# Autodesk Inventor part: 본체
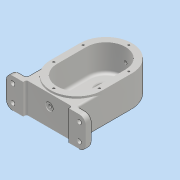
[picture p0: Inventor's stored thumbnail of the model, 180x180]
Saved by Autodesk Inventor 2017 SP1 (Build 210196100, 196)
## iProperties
Part Number: 본체
Material: 알루미늄 6061
Document SubType Name: Modeling
Designer: MRC
Density: 2.7 g/cm^3
Appearance: 알루미늄 - 평지
Mass: 756.449 g
Surface Area: 582.679 cm^2
Volume: 280.166 cm^3
Author: MRC
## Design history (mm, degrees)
sketch "스케치4"
  geometry: L1 (0, 0)-(0, -87); L2 (-40, 0)-(-40, -82); L3 (40, -82)-(40, 0); L4 (-40, -82)-(-61, -82); L5 (-61, -82)-(-61, -92); L6 (-61, -92)-(-35, -92); L7 (-35, -92)-(-35, -87); L8 (-35, -87)-(35, -87); L9 (35, -87)-(35, -92); L10 (35, -92)-(61, -92); L11 (61, -92)-(61, -82); L12 (61, -82)-(40, -82); A1 r 40 centre (0, 0) between (40, 0) and (-40, 0); 1 further point
  constraints: 26 end point, 7 perpendicular, 3 point on line, 2 midpoint, 2 point on circle, 2 tangent, 2 vertical, 1 centre point, 1 horizontal, 1 parallel
  dimensions: "d17" = 40 radius of A1; "d18" = 10 distance of L10.end L11.end; "d19" = 70 distance of L7.end L8.end; "d20" = 122 distance between parallel lines of L5 L11; "d21" = 61 distance from line of point (0, -43.5) L5; "d22" = 92 distance from line of L10 L1.start; "d23" = 5 distance of L8.end L9.end
extrude "돌출4" new body sketch "스케치4" distance "d24" = 46; taper "d25" = 0 deg
sketch "스케치5"
  geometry: L1 (0, 0)-(0, -45); L2 (-40, 0)-(-40, -45); L3 (40, -45)-(40, 0); A1 r 40 centre (0, 0) between (40, 0) and (-40, 0) reference; A2 r 40 centre (0, 0) between (40, 0) and (-40, 0); A3 r 40 centre (0, -45) between (-40, -45) and (40, -45); 1 further point
  constraints: 8 end point, 4 point on circle, 4 tangent, 2 centre point, 1 concentric, 1 midpoint, 1 parallel, 1 vertical
  dimensions: "d26" = 45 distance of L1.start L1.end
extrude "돌출5" join sketch "스케치5" distance "d27" = 3; taper "d28" = 0 deg
sketch "스케치6"
  geometry: L1 (0, 0)-(0, -45); L2 (-26, 0)-(-26, -45); L3 (26, -45)-(26, 0); A1 r 40 centre (0, 0) between (40, 0) and (-40, 0) reference; A2 r 26 centre (0, 0) between (26, 0) and (-26, 0); A3 r 26 centre (0, -45) between (-26, -45) and (26, -45); 1 further point
  constraints: 8 end point, 4 point on circle, 4 tangent, 2 centre point, 1 midpoint, 1 parallel, 1 vertical
  dimensions: "d29" = 26 radius of A2; "d30" = 45 distance of L1.start L1.end
extrude "돌출6" join sketch "스케치6" distance "d31" = 11; taper "d32" = 0 deg
sketch "스케치7"
  geometry: L1 (26, -45)-(26, 0) reference; L2 (-26, -45)-(-26, 0) reference; L3 (-26, -30)-(26, -30); A1 r 26 centre (0, 0) between (26, 0) and (-26, 0) reference
  constraints: 2 end point, 2 point on line, 1 perpendicular
  dimensions: "d33" = 30 distance from line of L3 A1.centre
extrude "돌출7" cut sketch "스케치7" distance "d34" = 3; taper "d35" = 0 deg
sketch "스케치8"
  geometry: L1 (0, 0)-(0, -45); L2 (-30, 0)-(-30, -45); L3 (30, -45)-(30, 0); A1 r 40 centre (0, -45) between (-40, -45) and (40, -45) reference; A2 r 40 centre (0, 0) between (40, 0) and (-40, 0) reference; A3 r 30 centre (0, 0) between (30, 0) and (-30, 0); A4 r 30 centre (0, -45) between (-30, -45) and (30, -45); 1 further point
  constraints: 8 end point, 4 point on circle, 4 tangent, 2 centre point, 1 midpoint, 1 parallel, 1 vertical
  dimensions: "d36" = 30 radius of A3
extrude "돌출8" cut sketch "스케치8" distance "d37" = 41; taper "d38" = 0 deg
hole "구멍1" diameter "d41" = 20; stored, may be unused: countersink angle "d45" = 90 deg, drill point angle "d47" = 0 deg; dims "d39" = 10, "d40" = 10, "d42" = 6, "d43" = 28, "d44" = 8, "d46" = 12
hole "구멍2" diameter "d50" = 22; stored, may be unused: countersink angle "d54" = 90 deg, drill point angle "d56" = 0 deg; dims "d48" = 10, "d49" = 10, "d51" = 6, "d52" = 28, "d53" = 8, "d55" = 100
sketch "스케치9"
  geometry: C1 r 11 at (0, 0) reference; C2 r 14 at (0, 0); A1 r 26 centre (0, 0) between (26, 0) and (-26, 0) reference
  constraints: 1 centre point, 1 coincident
  dimensions: "d57" = 28 diameter of C2
extrude "돌출9" cut sketch "스케치9" distance "d58" = 4; taper "d59" = 0 deg
fillet "모깎기4" dims "d60" = 10, "d61" = 5
sketch "스케치10"
  geometry: L1 (-101, 36)-(-101, 10) reference; L2 (-80, 0)-(-91, 0) reference; L3 (-80, 46)-(-80, 0) reference; L4 (-80, 46)-(-91, 46) reference; A1 r 10 centre (11, 36) between (21, 36) and (11, 46) reference; A2 r 10 centre (11, 10) between (11, 0) and (21, 10) reference; A3 r 10 centre (-91, 36) between (-91, 46) and (-101, 36) reference; A4 r 10 centre (-91, 10) between (-101, 10) and (-91, 0) reference; 1 further point
hole "구멍3" sketch "스케치10" at (-91, 10), (11, 36), (11, 10), (-91, 36) diameter "d62" = 6.6; stored, may be unused: countersink angle "d66" = 90 deg, drill point angle "d68" = 0 deg; dims "d63" = 6, "d64" = 11, "d65" = 2, "d67" = 10
node "작업 평면1"
sketch "스케치11"
  geometry: L1 (75, 49)-(-5, 49) reference; C1 r 6 at (35, 28); 1 further point
  constraints: 1 centre point, 1 vertical alignment
  dimensions: "d70" = 12 diameter of C1; "d71" = 21 distance from line of L1 C1.centre
extrude "돌출10" join sketch "스케치11" stored distance "d72" = 4; taper "d73" = 0 deg
hole "구멍4" diameter "d76" = 4.917; stored, may be unused: countersink angle "d80" = 90 deg, drill point angle "d82" = 0 deg; dims "d74" = 10, "d75" = 10, "d77" = 12, "d78" = 11, "d79" = 2, "d81" = 17.1
sketch "스케치12"
  geometry: L1 (0, 0)-(70, 0) reference; L2 (75, 49)-(-5, 49) reference; 3 further points
  constraints: 1 midpoint, 1 vertical alignment
  dimensions: "d83" = 21 distance from line of point (35, 28) L2
hole "구멍5" sketch "스케치12" at (35, 28) diameter "d84" = 4.917; stored, may be unused: countersink angle "d88" = 90 deg, drill point angle "d90" = 0 deg; dims "d85" = 12, "d86" = 12, "d87" = 1, "d89" = 17.1
sketch "스케치13"
  geometry: C1 r 14 at (0, 0) reference; 1 further point
  constraints: 1 vertical alignment
  dimensions: "d91" = 20 distance of C1.centre point (0, 20)
hole "구멍6" sketch "스케치13" at (0, 20) diameter "d92" = 3.242; stored, may be unused: countersink angle "d96" = 90 deg, drill point angle "d98" = 118 deg; dims "d93" = 8, "d94" = 12, "d95" = 1, "d97" = 10
sketch "스케치14"
  geometry: A1 r 30 centre (0, 0) between (30, 0) and (-30, 0) reference; 1 further point
  constraints: 1 vertical alignment
  dimensions: "d102" = 35 distance of A1.centre point (0, 35)
hole "구멍7" sketch "스케치14" at (0, 35) diameter "d103" = 3.242; stored, may be unused: countersink angle "d107" = 90 deg, drill point angle "d109" = 118 deg; dims "d104" = 8, "d105" = 12, "d106" = 1, "d108" = 10
sketch "스케치15"
  geometry: L1 (0, 0)-(0, -45); L2 (-35, 0)-(-35, -45); L3 (35, -45)-(35, 0); A1 r 40 centre (0, -45) between (-40, -45) and (40, -45) reference; A2 r 40 centre (0, 0) between (40, 0) and (-40, 0) reference; A3 r 35 centre (0, 0) between (35, 0) and (-35, 0); A4 r 35 centre (0, -45) between (-35, -45) and (35, -45); 6 further points
  constraints: 8 end point, 5 point on circle, 4 coincident, 4 tangent, 2 centre point, 1 midpoint, 1 parallel, 1 vertical
  dimensions: "d110" = 70 diameter of A4
hole "구멍8" sketch "스케치15" at (-35, 0), (35, 0), (35, -45), (-35, -45), (0, -80) diameter "d111" = 3.242; stored, may be unused: countersink angle "d115" = 90 deg, drill point angle "d117" = 118 deg; dims "d112" = 8, "d113" = 12, "d114" = 1, "d116" = 10
fillet "모깎기5" dims "d118" = 0.3
chamfer "모따기1" distance "d119" = 1; stored, may be unused: second distance "d120" = 2, angle "d121" = 45 deg
fillet "모깎기6" dims "d122" = 3
sketch "스케치16"
  geometry: L1 (32, -87)-(-32, -87) reference; L2 (-51, -92)-(-61, -92) reference; 2 further points
  constraints: 1 midpoint, 1 vertical alignment, 1 other
  dimensions: "d123" = 12 distance from line of point (0, -80) L2
feature "엠보싱1" sketch "스케치16" dims "d124" = 0.5, "d125" = 0
node "솔리드2"
pattern_circular "원형 패턴1" dims angle "d100" = 360 deg
node "투영된 루프1"
